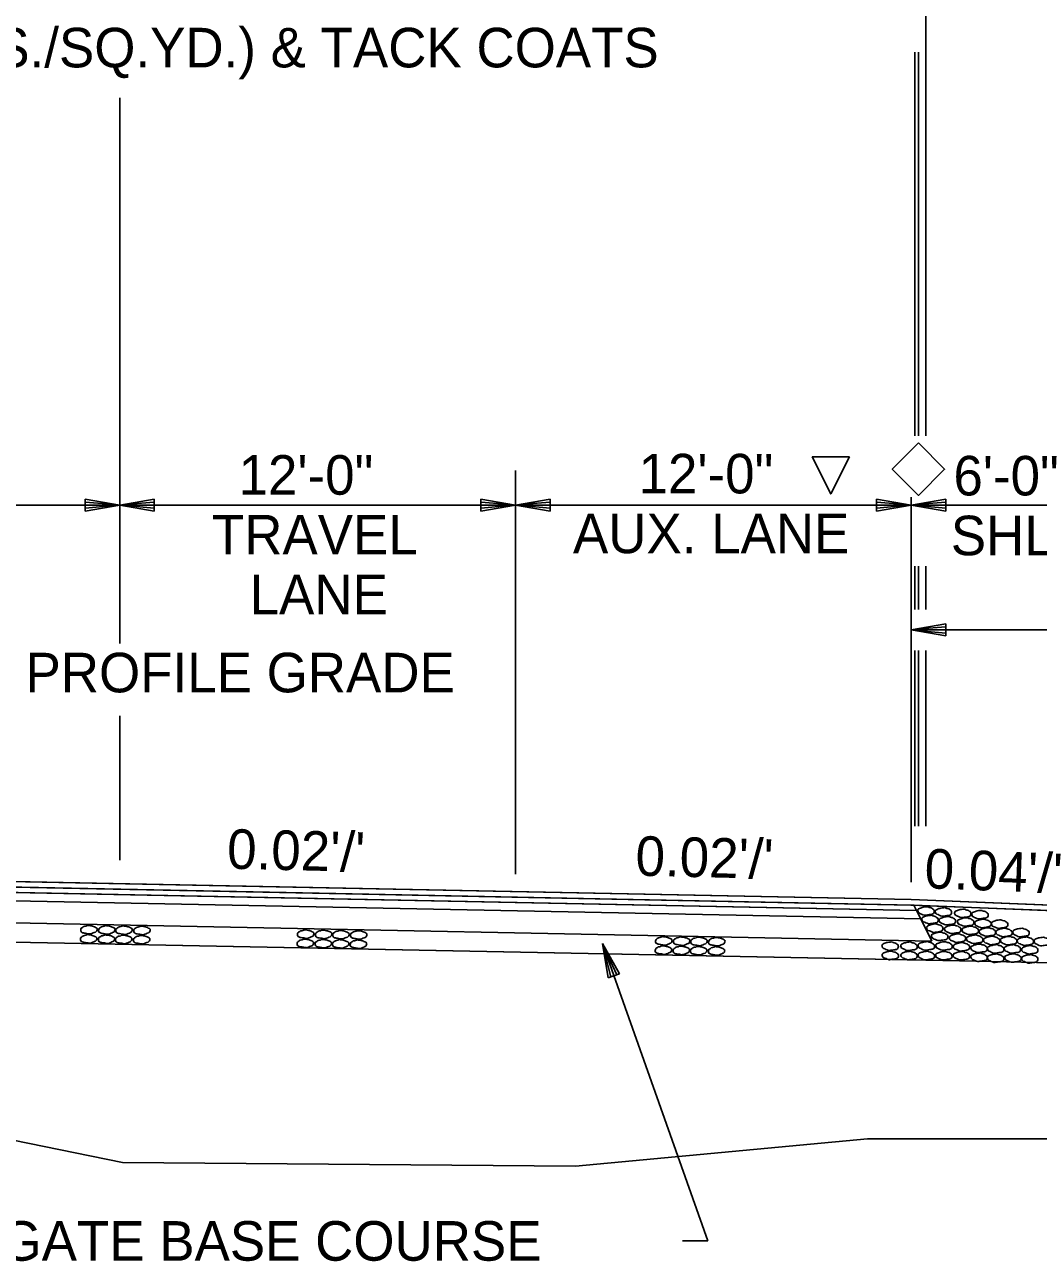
# Model space of a CAD drawing. Extents: x 1734743 to 1735935, y 759845 to 763831.
# Drawn here: x 1735806.82 to 1735837.56, y 763219.46 to 763256.95 of the extents above; entities that cross this region are included whole.
import ezdxf

# ---------------------------------------------------------------- set-up
doc = ezdxf.new("R2010")
doc.units = 0
for name, color, linetype in [('1', 7, 'Continuous'), ('10', 7, 'Continuous'), ('19', 7, 'Continuous'), ('Level 1', 7, 'Continuous'), ('R_Prop Surface', 7, 'Continuous')]:
    doc.layers.add(name, color=color, linetype=linetype)

# ---------------------------------------------------------------- blocks, each defined once
blk = doc.blocks.new('ROCKS')
at = {"layer": '1'}
blk.add_spline([(0.013, 0.06), (0.053, 0.053), (0.107, 0.033), (0.133, 0.013), (0.133, -0.007), (0.12, -0.033), (0.107, -0.04), (0.073, -0.053), (0.033, -0.067), (0.013, -0.067), (-0.02, -0.06), (-0.06, -0.053), (-0.087, -0.047), (-0.113, -0.02), (-0.113, -0.007), (-0.107, 0.02), (-0.087, 0.033), (-0.067, 0.047), (-0.033, 0.053), (-0.02, 0.06), (0.013, 0.06)], degree=3, dxfattribs=at)

msp = doc.modelspace()

# ---------------------------------------------------------------- linework, layer by layer
at = {"layer": '10'}
for points in [[(1735833.924, 763244.271), (1735834.72, 763243.476), (1735833.924, 763242.68), (1735833.129, 763243.476)], [(1735831.831, 763243.849), (1735831.268, 763242.724), (1735830.706, 763243.849)]]:
    msp.add_lwpolyline(points, close=True, dxfattribs=at)
at = {"layer": '19'}
for p, q in [((1735834.15, 763244.492), (1735834.15, 763258.211)), ((1735833.82, 763244.492), (1735833.82, 763256.119)), ((1735833.924, 763244.492), (1735833.924, 763256.119)), ((1735809.701, 763238.191), (1735809.701, 763254.739)), ((1735821.701, 763231.194), (1735821.701, 763243.437)), ((1735833.701, 763230.954), (1735833.701, 763242.626)), ((1735809.701, 763242.387), (1735797.701, 763242.387)), ((1735808.651, 763242.571), (1735808.651, 763242.203)), ((1735809.701, 763242.387), (1735808.651, 763242.571)), ((1735809.421, 763242.413), (1735808.651, 763242.475)), ((1735808.651, 763242.203), (1735809.701, 763242.387)), ((1735808.651, 763242.291), (1735809.421, 763242.361)), ((1735810.751, 763242.571), (1735809.701, 763242.387)), ((1735833.701, 763242.387), (1735809.701, 763242.387)), ((1735809.701, 763242.387), (1735810.751, 763242.203)), ((1735810.751, 763242.474), (1735809.981, 763242.413)), ((1735809.981, 763242.361), (1735810.751, 763242.291)), ((1735810.751, 763242.203), (1735810.751, 763242.571)), ((1735820.651, 763242.571), (1735820.651, 763242.203)), ((1735821.701, 763242.387), (1735820.651, 763242.571)), ((1735821.421, 763242.413), (1735820.651, 763242.475)), ((1735820.651, 763242.203), (1735821.701, 763242.387)), ((1735820.651, 763242.291), (1735821.421, 763242.361)), ((1735822.751, 763242.571), (1735821.701, 763242.387)), ((1735821.701, 763242.387), (1735822.751, 763242.203)), ((1735822.751, 763242.474), (1735821.981, 763242.413)), ((1735821.981, 763242.361), (1735822.751, 763242.291)), ((1735822.751, 763242.203), (1735822.751, 763242.571)), ((1735832.651, 763242.571), (1735832.651, 763242.203)), ((1735833.701, 763242.387), (1735832.651, 763242.571)), ((1735833.421, 763242.413), (1735832.651, 763242.475)), ((1735832.651, 763242.203), (1735833.701, 763242.387)), ((1735832.651, 763242.291), (1735833.421, 763242.361)), ((1735834.751, 763242.571), (1735833.701, 763242.387)), ((1735839.701, 763242.387), (1735833.701, 763242.387)), ((1735833.701, 763242.387), (1735834.751, 763242.203)), ((1735834.751, 763242.474), (1735833.981, 763242.413)), ((1735833.981, 763242.361), (1735834.751, 763242.291)), ((1735834.751, 763242.203), (1735834.751, 763242.571)), ((1735833.82, 763239.227), (1735833.82, 763240.536)), ((1735833.924, 763239.227), (1735833.924, 763240.536)), ((1735834.15, 763239.227), (1735834.15, 763240.536)), ((1735834.751, 763238.788), (1735833.701, 763238.604)), ((1735863.691, 763238.604), (1735833.701, 763238.604)), ((1735833.701, 763238.604), (1735834.751, 763238.421)), ((1735834.751, 763238.692), (1735833.981, 763238.631)), ((1735833.981, 763238.578), (1735834.751, 763238.508)), ((1735834.751, 763238.421), (1735834.751, 763238.788)), ((1735833.82, 763232.653), (1735833.82, 763237.981)), ((1735833.924, 763232.653), (1735833.924, 763237.981)), ((1735834.15, 763232.653), (1735834.15, 763237.981)), ((1735809.701, 763231.62), (1735809.701, 763236)), ((1735797.701, 763231.149), (1735833.701, 763230.429)), ((1735797.536, 763230.819), (1735833.869, 763230.092)), ((1735833.869, 763230.092), (1735797.536, 763230.819)), ((1735797.701, 763230.982), (1735833.697, 763230.262)), ((1735797.412, 763230.571), (1735833.995, 763229.84)), ((1735797.412, 763230.571), (1735833.995, 763229.84)), ((1735833.995, 763229.84), (1735797.412, 763230.571)), ((1735833.696, 763230.262), (1735839.786, 763230.019)), ((1735833.701, 763230.429), (1735839.701, 763230.189)), ((1735797.082, 763229.911), (1735834.332, 763229.166)), ((1735797.082, 763229.911), (1735834.332, 763229.166)), ((1735833.995, 763229.84), (1735833.869, 763230.092)), ((1735834.332, 763229.166), (1735833.995, 763229.84)), ((1735797.688, 763229.316), (1735835.688, 763228.556)), ((1735797.701, 763229.315), (1735835.7, 763228.556)), ((1735824.339, 763229.1), (1735827.539, 763220.078)), ((1735824.517, 763228.052), (1735824.339, 763229.1)), ((1735824.339, 763229.1), (1735824.862, 763228.171)), ((1735824.599, 763228.082), (1735824.406, 763228.828)), ((1735824.452, 763228.845), (1735824.773, 763228.145)), ((1735835.688, 763228.556), (1735851.384, 763228.242)), ((1735824.862, 763228.171), (1735824.517, 763228.052)), ((1735809.784, 763222.456), (1735800.684, 763224.323)), ((1735823.527, 763222.341), (1735832.379, 763223.176)), ((1735832.379, 763223.176), (1735844.79, 763223.176)), ((1735809.784, 763222.456), (1735823.527, 763222.341)), ((1735826.766, 763220.078), (1735827.539, 763220.078))]:
    msp.add_line(p, q, dxfattribs=at)
for points in [[(1735833.786, 763230.259), (1735797.701, 763230.982), (1735797.701, 763230.982), (1735797.616, 763230.979), (1735797.616, 763230.979), (1735793.619, 763230.819), (1735793.704, 763230.989), (1735797.701, 763231.149), (1735833.701, 763230.429), (1735839.701, 763230.189), (1735839.786, 763230.019), (1735839.786, 763230.019), (1735833.786, 763230.259), (1735833.786, 763230.259), (1735833.786, 763230.259)], [(1735833.869, 763230.092), (1735797.536, 763230.819), (1735797.536, 763230.819), (1735797.616, 763230.979), (1735797.616, 763230.979), (1735797.701, 763230.982), (1735833.696, 763230.262), (1735833.786, 763230.259), (1735833.786, 763230.259), (1735833.869, 763230.092), (1735833.869, 763230.092), (1735833.869, 763230.092)]]:
    msp.add_lwpolyline(points, dxfattribs=at)
at = {"layer": 'R_Prop Surface'}
msp.add_line((1735833.786, 763230.259), (1735834.332, 763229.166), dxfattribs=at)

# ---------------------------------------------------------------- block references
at = {"layer": 'Level 1'}
for p, xscale, yscale, rotation in [((1735834.173, 763230.086), 2.0116542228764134, -2.011654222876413, 177.9586193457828), ((1735834.298, 763229.827), 2.0116542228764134, -2.011654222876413, 177.9586193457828), ((1735834.705, 763230.057), 2.0116542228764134, -2.011654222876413, 177.9586193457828), ((1735834.824, 763229.792), 2.0116542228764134, -2.011654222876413, 177.9586193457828), ((1735835.291, 763230.014), 2.011654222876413, -2.0116542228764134, 177.95871721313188), ((1735835.378, 763229.752), 2.011654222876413, -2.0116542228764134, 177.95871721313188), ((1735835.81, 763229.975), 2.011654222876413, -2.0116542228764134, 177.95871721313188), ((1735808.746, 763229.52), 2.011654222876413, 2.011654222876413, 0.9336332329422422), ((1735809.289, 763229.512), 2.011654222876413, 2.011654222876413, 0.9336332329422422), ((1735809.811, 763229.504), 2.011654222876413, 2.011654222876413, 0.9336332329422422), ((1735810.354, 763229.495), 2.011654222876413, 2.011654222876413, 0.9336332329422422), ((1735815.323, 763229.384), 2.011654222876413, 2.011654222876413, 0.9336332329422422), ((1735815.866, 763229.376), 2.011654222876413, 2.011654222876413, 0.9336332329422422), ((1735816.388, 763229.368), 2.011654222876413, 2.011654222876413, 0.9336332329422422), ((1735834.443, 763229.566), 2.0116542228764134, -2.011654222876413, 177.9586193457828), ((1735834.987, 763229.531), 2.0116542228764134, -2.011654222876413, 177.9586193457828), ((1735835.517, 763229.498), 2.0116542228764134, -2.011654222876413, 177.9586193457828), ((1735835.901, 763229.707), 2.011654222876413, -2.0116542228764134, 177.95871721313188), ((1735836.039, 763229.45), 2.011654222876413, -2.0116542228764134, 177.95871721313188), ((1735836.406, 763229.688), 2.011654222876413, -2.0116542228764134, 177.95871721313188), ((1735836.544, 763229.434), 2.011654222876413, -2.0116542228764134, 177.95871721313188), ((1735837.056, 763229.432), 2.011654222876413, -2.0116542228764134, 177.95871721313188), ((1735808.736, 763229.24), 2.011654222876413, 2.011654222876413, 0.9336332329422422), ((1735809.28, 763229.232), 2.011654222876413, 2.011654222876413, 0.9336332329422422), ((1735809.801, 763229.224), 2.011654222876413, 2.011654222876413, 0.9336332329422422), ((1735810.344, 763229.215), 2.011654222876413, 2.011654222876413, 0.9336332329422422), ((1735815.313, 763229.104), 2.011654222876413, 2.011654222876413, 0.9336332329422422), ((1735815.856, 763229.096), 2.011654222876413, 2.011654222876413, 0.9336332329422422), ((1735816.378, 763229.088), 2.011654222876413, 2.011654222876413, 0.9336332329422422), ((1735816.921, 763229.079), 2.011654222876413, 2.011654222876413, 0.9336332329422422), ((1735816.93, 763229.359), 2.011654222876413, 2.011654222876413, 0.9336332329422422), ((1735826.182, 763229.18), 2.011654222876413, 2.011654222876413, 0.9336332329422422), ((1735826.725, 763229.171), 2.011654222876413, 2.011654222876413, 0.9336332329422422), ((1735827.247, 763229.163), 2.011654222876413, 2.011654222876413, 0.9336332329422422), ((1735827.789, 763229.155), 2.011654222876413, 2.011654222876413, 0.9336332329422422), ((1735833.089, 763229.018), 2.0116542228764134, -2.011654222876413, 177.9586193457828), ((1735833.659, 763229.016), 2.0116542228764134, -2.011654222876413, 177.9586193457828), ((1735834.183, 763229.027), 2.0116542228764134, -2.011654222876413, 177.9586193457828), ((1735834.59, 763229.317), 2.0116542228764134, -2.011654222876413, 177.9586193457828), ((1735834.718, 763229.025), 2.0116542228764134, -2.011654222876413, 177.9586193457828), ((1735835.131, 763229.263), 2.0116542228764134, -2.011654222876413, 177.9586193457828), ((1735835.252, 763229), 2.0116542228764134, -2.011654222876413, 177.9586193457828), ((1735835.652, 763229.229), 2.0116542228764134, -2.011654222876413, 177.9586193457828), ((1735836.169, 763229.192), 2.011654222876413, -2.0116542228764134, 177.95871721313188), ((1735836.68, 763229.187), 2.011654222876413, -2.0116542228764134, 177.95871721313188), ((1735837.192, 763229.171), 2.011654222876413, -2.0116542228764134, 177.95871721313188), ((1735837.701, 763229.159), 2.011654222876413, -2.0116542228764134, 177.95871721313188), ((1735826.172, 763228.9), 2.011654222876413, 2.011654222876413, 0.9336332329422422), ((1735826.715, 763228.891), 2.011654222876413, 2.011654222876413, 0.9336332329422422), ((1735827.237, 763228.883), 2.011654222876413, 2.011654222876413, 0.9336332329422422), ((1735827.78, 763228.875), 2.011654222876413, 2.011654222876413, 0.9336332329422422), ((1735833.093, 763228.738), 2.0116542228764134, -2.011654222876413, 177.9586193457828), ((1735833.663, 763228.736), 2.0116542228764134, -2.011654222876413, 177.9586193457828), ((1735834.182, 763228.734), 2.0116542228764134, -2.011654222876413, 177.9586193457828), ((1735834.717, 763228.732), 2.0116542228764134, -2.011654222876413, 177.9586193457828), ((1735835.251, 763228.73), 2.0116542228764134, -2.011654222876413, 177.9586193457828), ((1735835.784, 763228.684), 2.0116542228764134, -2.011654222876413, 177.9586193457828), ((1735835.785, 763228.955), 2.0116542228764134, -2.011654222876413, 177.9586193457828), ((1735836.286, 763228.935), 2.011654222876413, -2.0116542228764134, 177.95871721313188), ((1735836.286, 763228.654), 2.011654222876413, -2.0116542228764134, 177.95871721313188), ((1735836.797, 763228.935), 2.011654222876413, -2.0116542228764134, 177.95871721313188), ((1735836.811, 763228.659), 2.011654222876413, -2.0116542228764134, 177.95871721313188), ((1735837.324, 763228.91), 2.011654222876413, -2.0116542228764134, 177.95871721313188), ((1735837.324, 763228.635), 2.011654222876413, -2.0116542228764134, 177.95871721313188)]:
    msp.add_blockref('ROCKS', p, dxfattribs=dict(at, xscale=xscale, yscale=yscale, rotation=rotation))

# ---------------------------------------------------------------- texts
at = {"layer": '19'}
for s, p in [('(880 LBS./SQ.YD.) & TACK COATS', (1735800.277, 763255.658)), ('12\'-0"', (1735813.306, 763242.702)), ('12\'-0" ', (1735825.437, 763242.741)), ('6\'-0"', (1735834.987, 763242.679)), ('TRAVEL', (1735812.498, 763240.89)), ('AUX. LANE', (1735823.448, 763240.928)), ('SHLD.', (1735834.907, 763240.866)), ('LANE', (1735813.641, 763239.077)), ('PROFILE GRADE', (1735806.845, 763236.71))]:
    msp.add_text(s, height=1.2, dxfattribs=at).set_placement(p)
for s, rotation, p in [("0.02'/'", 358.6386, (1735812.948, 763231.366)), ("0.02'/'", 358.6386, (1735825.334, 763231.154)), ("0.04'/'", 357.8398, (1735834.095, 763230.774)), ('36\'-0" AGGREGATE BASE COURSE', 360, (1735795.757, 763219.478))]:
    msp.add_text(s, height=1.2, rotation=rotation, dxfattribs=at).set_placement(p)

doc.saveas('drawing.dxf')
